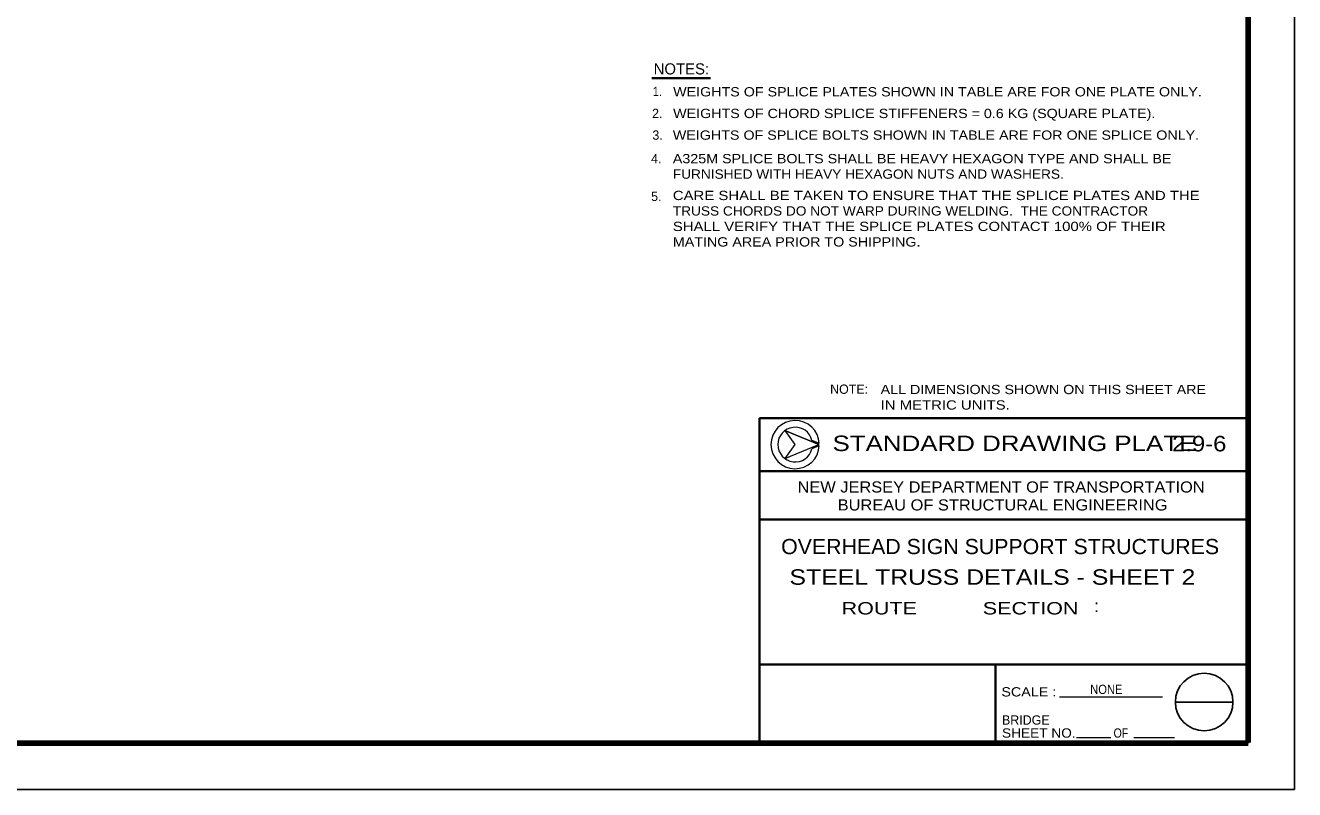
# Model space of a CAD drawing. Extents: x 312601.858 to 312602.699, y 144420.109 to 144420.704.
# Drawn here: x 312602.2889 to 312602.6988, y 144420.1095 to 144420.3565 of the extents above; entities that cross this region are included whole.
import ezdxf
from ezdxf.enums import TextEntityAlignment as Align

# ---------------------------------------------------------------- set-up
doc = ezdxf.new("R2010")
doc.units = 0
doc.header["$LTSCALE"] = 0.0012
for name, color, linetype, lineweight in [('1', 7, 'Continuous', 25), ('2', 7, 'Continuous', 13), ('39', 7, 'Continuous', 13)]:
    doc.layers.add(name, color=color, linetype=linetype, lineweight=lineweight)
doc.layers.add('4', color=7, linetype='Continuous')

msp = doc.modelspace()

# ---------------------------------------------------------------- linework, layer by layer
at = {"layer": '1', "lineweight": 13}
msp.add_line((312602.543, 144420.2197), (312602.5453, 144420.2207), dxfattribs=at)
for points in [[(312602.5451, 144420.221), (312602.5342, 144420.2255), (312602.5451, 144420.221)], [(312602.5453, 144420.2213), (312602.543, 144420.2223), (312602.5429, 144420.2223)]]:
    msp.add_lwpolyline(points, dxfattribs=at)
for points in [[(312602.5451, 144420.221), (312602.5342, 144420.2255), (312602.5374, 144420.221), (312602.5342, 144420.2165)], [(312602.5374, 144420.221), (312602.5342, 144420.2165), (312602.5451, 144420.221), (312602.5342, 144420.2255)]]:
    msp.add_lwpolyline(points, close=True, dxfattribs=at)
for radius, start, end in [(0.007803, 2.21392, 357.78608), (0.0056, 13.69411, 346.30589)]:
    msp.add_arc((312602.5375, 144420.221), radius, start, end, dxfattribs=at)
at = {"layer": '2', "lineweight": 35}
msp.add_line((312602.4912, 144420.3394), (312602.5102, 144420.3394), dxfattribs=at)
at = {"layer": '39', "lineweight": 25}
for p, q in [((312602.6988, 144420.1095), (312602.6988, 144420.7035)), ((312602.6789, 144420.1378), (312602.6603, 144420.1378)), ((312602.452, 144420.1245), (312602.6838, 144420.1245)), ((312601.8578, 144420.1095), (312602.6988, 144420.1095))]:
    msp.add_line(p, q, dxfattribs=at)
at = {"layer": '39', "lineweight": 158}
for p, q in [((312602.6838, 144420.1247), (312602.6838, 144420.6645)), ((312601.9088, 144420.1245), (312602.6838, 144420.1245))]:
    msp.add_line(p, q, dxfattribs=at)
at = {"layer": '39', "lineweight": 35}
for p, q in [((312602.526, 144420.1245), (312602.526, 144420.2295)), ((312602.526, 144420.2295), (312602.6838, 144420.2295)), ((312602.6838, 144420.2295), (312602.6838, 144420.1245)), ((312602.526, 144420.2124), (312602.6838, 144420.2124)), ((312602.526, 144420.1968), (312602.6838, 144420.1968)), ((312602.526, 144420.1499), (312602.6838, 144420.1499)), ((312602.6022, 144420.1248), (312602.6022, 144420.1499))]:
    msp.add_line(p, q, dxfattribs=at)
at = {"layer": '39'}
for p, q in [((312602.6022, 144420.1499), (312602.6838, 144420.1499)), ((312602.6022, 144420.1248), (312602.6022, 144420.1499)), ((312602.6022, 144420.1248), (312602.6022, 144420.1499)), ((312602.6229, 144420.1395), (312602.6561, 144420.1395)), ((312602.6284, 144420.1263), (312602.6394, 144420.1263)), ((312602.6469, 144420.1263), (312602.66, 144420.1263))]:
    msp.add_line(p, q, dxfattribs=at)
msp.add_lwpolyline([(312602.5451, 144420.221), (312602.5342, 144420.2255), (312602.5374, 144420.221), (312602.5342, 144420.2165)], close=True, dxfattribs=at)
at = {"layer": '39', "lineweight": 25}
msp.add_circle((312602.6696, 144420.1378), 0.0093, dxfattribs=at)

# ---------------------------------------------------------------- texts
at = {"layer": '2'}
for s, height, p in [('NOTES:', 0.0036, (312602.4918, 144420.3406)), ('2.', 0.003, (312602.4913, 144420.3265)), ('3.', 0.003, (312602.4914, 144420.3195)), ('4.', 0.003, (312602.491, 144420.3119)), ('5.', 0.003, (312602.491, 144420.2997))]:
    msp.add_text(s, height=height, dxfattribs=at).set_placement(p)
for s, width, p in [('1.', 0.9, (312602.4915, 144420.3336)), ('WEIGHTS OF SPLICE PLATES SHOWN IN TABLE ARE FOR ONE PLATE ONLY.', 1.15, (312602.4981, 144420.3335)), ('WEIGHTS OF CHORD SPLICE STIFFENERS = 0.6 KG (SQUARE PLATE).', 1.15, (312602.4981, 144420.3265)), ('WEIGHTS OF SPLICE BOLTS SHOWN IN TABLE ARE FOR ONE SPLICE ONLY.', 1.15, (312602.498, 144420.3195)), ('A325M SPLICE BOLTS SHALL BE HEAVY HEXAGON TYPE AND SHALL BE', 1.15, (312602.498, 144420.3119)), ('FURNISHED WITH HEAVY HEXAGON NUTS AND WASHERS.', 1.1, (312602.498, 144420.3069)), ('CARE SHALL BE TAKEN TO ENSURE THAT THE SPLICE PLATES AND THE ', 1.2, (312602.498, 144420.3)), ('TRUSS CHORDS DO NOT WARP DURING WELDING.  THE CONTRACTOR', 1.1, (312602.498, 144420.295)), ('SHALL VERIFY THAT THE SPLICE PLATES CONTACT 100% OF THEIR', 1.2, (312602.498, 144420.29)), ('MATING AREA PRIOR TO SHIPPING.', 1.15, (312602.498, 144420.285))]:
    msp.add_text(s, height=0.003, dxfattribs=dict(at, width=width)).set_placement(p)
for s, height, width, p in [('2.9-6', 0.005, 1.15, (312602.668, 144420.2188)), ('OVERHEAD SIGN SUPPORT STRUCTURES', 0.0049, 1.05, (312602.6037, 144420.1856)), ('STEEL TRUSS DETAILS - SHEET 2', 0.005, 1.2, (312602.6012, 144420.1757)), ('NONE', 0.003, 0.9, (312602.638, 144420.1404))]:
    msp.add_text(s, height=height, dxfattribs=dict(at, width=width)).set_placement(p, align=Align.CENTER)
at = {"layer": '39'}
for s, height, width, p in [('STANDARD DRAWING PLATE       ', 0.005, 1.25, (312602.61645, 144420.2189)), ('NEW JERSEY DEPARTMENT OF TRANSPORTATION', 0.003599, 1.1, (312602.604, 144420.2055)), ('BUREAU OF STRUCTURAL ENGINEERING', 0.0036, 1.1, (312602.6045, 144420.1997)), ('ROUTE           SECTION', 0.004, 1.3, (312602.59075, 144420.1661)), ('SCALE :', 0.003, 1.15, (312602.61295, 144420.1396)), ('OF', 0.003, 0.85, (312602.6427, 144420.1263))]:
    msp.add_text(s, height=height, dxfattribs=dict(at, width=width)).set_placement(p, align=Align.CENTER)
for p in [(312602.569737, 144420.1671), (312602.634837, 144420.1669)]:
    msp.add_text(':', height=0.004, dxfattribs=at).set_placement(p, align=Align.CENTER)
msp.add_text('BRIDGE', height=0.003, dxfattribs=at).set_placement((312602.6043, 144420.1305))
at = {"layer": '39', "width": 1.1}
msp.add_text('SHEET NO.', height=0.003, dxfattribs=at).set_placement((312602.6043, 144420.1263))
at = {"layer": '4'}
msp.add_text('NOTE:', height=0.003, dxfattribs=at).set_placement((312602.5488, 144420.2374))
for s, width, p in [('ALL DIMENSIONS SHOWN ON THIS SHEET ARE', 1.15, (312602.5651, 144420.2373)), ('IN METRIC UNITS.', 1.2, (312602.5651, 144420.2323))]:
    msp.add_text(s, height=0.003, dxfattribs=dict(at, width=width)).set_placement(p)

doc.saveas('drawing.dxf')
